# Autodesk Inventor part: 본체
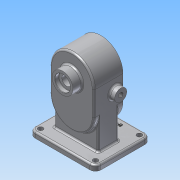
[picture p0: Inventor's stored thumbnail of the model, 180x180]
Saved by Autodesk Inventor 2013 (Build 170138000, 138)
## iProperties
Created: 2020-09
Part Number: 본체
Material: 알루미늄 6061
Document SubType Name: Modeling
Designer: Administrator
Density: 2.71 g/cm^3
Mass: 1445.8 g
Surface Area: 785.637 cm^2
Volume: 533.506 cm^3
Author: Administrator
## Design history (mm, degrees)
sketch "스케치1"
  geometry: L1 (-50, -60)-(50, -60); L2 (50, -60)-(50, 60); L3 (50, 60)-(-50, 60); L4 (-50, 60)-(-50, -60); L5 (-50, -60)-(50, 60); L6 (50, -60)-(-50, 60); 1 further point
  constraints: 12 end point, 2 midpoint, 2 parallel, 1 horizontal, 1 perpendicular
  dimensions: "d0" = 100 distance of L1.start L1.end; "d2" = 120 distance of L1.end L2.end
extrude "돌출1" new body sketch "스케치1" distance "d3" = 10; taper "d4" = 0 deg
sketch "스케치2"
  geometry: L1 (-40, 112)-(-40, 68); L2 (40, 112)-(40, 68); L3 (60, 0)-(-60, 0) reference; A1 r 40 centre (0, 112) between (40, 112) and (-40, 112); A2 r 40 centre (0, 68) between (-40, 68) and (40, 68); 2 further points
  constraints: 4 end point, 4 point on circle, 4 tangent, 2 centre point, 2 vertical alignment, 1 equal radius, 1 midpoint
  dimensions: "d5" = 80 diameter of A1; "d7" = 44 distance of A2.centre A1.centre; "d8" = 112 distance from line of L3 A1.centre
extrude "돌출2" join sketch "스케치2" distance "d9" = 20; taper "d11" = 0 deg; dims "d10" = 33, "d12" = 0
sketch "스케치3"
  geometry: C1 r 19 at (112, 0); A1 r 40 centre (112, 0) between (112, -40) and (112, 40) reference; 1 further point
  constraints: 1 centre point, 1 coincident
  dimensions: "d13" = 38 diameter of C1
extrude "돌출3" join sketch "스케치3" distance "d15" = 17; taper "d16" = 0 deg
sketch "스케치4"
  geometry: L1 (-112, -24)-(-68, -24); L2 (-112, 24)-(-68, 24); A1 r 40 centre (-112, 0) between (-112, 40) and (-112, -40) reference; A2 r 40 centre (-68, 0) between (-68, -40) and (-68, 40) reference; A3 r 24 centre (-112, 0) between (-112, -24) and (-112, 24); A4 r 24 centre (-68, 0) between (-68, -24) and (-68, 24); 1 further point
  constraints: 4 end point, 4 point on circle, 4 tangent, 2 centre point, 2 coincident, 1 equal radius
  dimensions: "d17" = 48 diameter of A3
extrude "돌출4" cut sketch "스케치4" distance "d19" = 29; taper "d20" = 0 deg
sketch "스케치5"
  geometry: C1 r 19 at (0, 0) reference; C2 r 14 at (0, 0); 1 further point
  constraints: 1 centre point, 1 coincident
  dimensions: "d21" = 28 diameter of C2
extrude "돌출5" cut sketch "스케치5" distance "d23" = 7.3; taper "d24" = 0 deg
sketch "스케치6"
  geometry: C1 r 12.5 at (-112, 0); A1 r 24 centre (-112, 0) between (-112, 24) and (-112, -24) reference; 1 further point
  constraints: 1 centre point, 1 coincident
  dimensions: "d25" = 25 diameter of C1
extrude "돌출6" cut sketch "스케치6" distance "d27" = 15; taper "d28" = 0 deg
sketch "스케치7"
  geometry: C1 r 14 at (0, 0) reference; C2 r 8.5 at (0, 0); 1 further point
  constraints: 1 centre point, 1 coincident
  dimensions: "d29" = 17 diameter of C2
extrude "돌출7" cut sketch "스케치7" stored distance "d31" = 15; taper "d32" = 0 deg
sketch "스케치8"
  geometry: C1 r 12.5 at (-68, 0); A1 r 24 centre (-68, 0) between (-68, -24) and (-68, 24) reference; 1 further point
  constraints: 1 centre point, 1 coincident
  dimensions: "d33" = 25 diameter of C1
extrude "돌출8" cut sketch "스케치8" distance "d35" = 15; taper "d36" = 0 deg
sketch "스케치9"
  geometry: L1 (-25, -40)-(12, -40); L2 (12, -40)-(12, 40); L3 (12, 40)-(-25, 40); L4 (-25, 40)-(-25, -40); L5 (-50, 60)-(-50, -60) reference; 2 further points
  constraints: 8 end point, 2 parallel, 1 horizontal, 1 horizontal alignment, 1 midpoint, 1 perpendicular
  dimensions: "d37" = 25 distance between parallel lines of L4 L5; "d38" = 37 distance of L2.end L3.end; "d39" = 80 distance of L1.end L2.end
extrude "돌출9" join sketch "스케치9" stored distance "d40" = 15; taper "d41" = 0 deg
fillet "모깎기1" dims "d42" = 3
fillet "모깎기2" dims "d43" = 10
fillet "모깎기3" dims "d44" = 3
fillet "모깎기4" dims "d45" = 3
fillet "모깎기5" dims "d46" = 3
fillet "모깎기6" dims "d47" = 3
fillet "모깎기7" dims "d48" = 3
chamfer "모따기1" distance "d49" = 0.7; stored, may be unused: second distance "d50" = 2, angle "d51" = 30 deg
chamfer "모따기2" distance "d52" = 1; stored, may be unused: second distance "d53" = 2, angle "d54" = 45 deg
chamfer "모따기3" distance "d55" = 1; stored, may be unused: second distance "d56" = 2, angle "d57" = 45 deg
sketch "스케치10"
  geometry: L1 (-50, 44)-(0, 44) reference; L2 (-60, -68)-(20, -68) reference; L3 (0, 44)-(0, 0) reference; C1 r 11 at (-14, 22); 2 further points
  constraints: 1 centre point, 1 midpoint
  dimensions: "d58" = 22 diameter of C1; "d92" = 22 distance from line of L1 C1.centre; "d93" = 14 distance from line of L3 C1.centre
extrude "돌출10" join sketch "스케치10" distance "d60" = 10; taper "d61" = 0 deg
sketch "스케치11"
  geometry: C1 r 11 at (0, 0) reference; 1 further point
hole "구멍1" sketch "스케치11" at (0, 0) diameter "d62" = 8.376; stored, may be unused: countersink angle "d66" = 90 deg, drill point angle "d68" = 0 deg; dims "d63" = 100, "d64" = 4, "d65" = 2, "d67" = 8
fillet "모깎기8" dims "d69" = 3
sketch "스케치12"
  geometry: A1 r 40 centre (-112, 0) between (-112, 40) and (-112, -40) reference; A2 r 40 centre (-68, 0) between (-68, -40) and (-68, 40) reference; A3 r 31 centre (-112, 0) between (-143, 0) and (-112, 31); A4 r 31 centre (-68, 0) between (-37, 0) and (-68, -31); 3 further points
  constraints: 6 point on circle, 2 centre point, 2 coincident
  dimensions: "d70" = 62 diameter of A3; "d72" = 62 diameter of A4
hole "구멍2" sketch "스케치12" at (-143, 0), (-37, 0), (-68, -31), (-68, 31), (-112, 31), (-112, -31) diameter "d73" = 4.134; stored, may be unused: countersink angle "d77" = 90 deg, drill point angle "d79" = 118 deg; dims "d74" = 10, "d75" = 4, "d76" = 2, "d78" = 12
fillet "모깎기9" dims "d80" = 3
sketch "스케치13"
  geometry: A1 r 10 centre (-40, -50) between (-50, -50) and (-40, -60) reference; A2 r 10 centre (-40, 50) between (-40, 60) and (-50, 50) reference; A3 r 10 centre (40, -50) between (40, -60) and (50, -50) reference; A4 r 10 centre (40, 50) between (50, 50) and (40, 60) reference; 1 further point
hole "구멍3" sketch "스케치13" at (-40, -50), (-40, 50), (40, 50), (40, -50) diameter "d81" = 9; stored, may be unused: countersink angle "d85" = 90 deg, drill point angle "d87" = 118 deg; dims "d82" = 10, "d83" = 4, "d84" = 2, "d86" = 12
sketch "스케치14"
  geometry: L1 (50, -50)-(50, 50) reference; L2 (-40, -60)-(40, -60) reference; 2 further points
  constraints: 1 other
  dimensions: "d88" = 12 distance from line of L1 point (38, 0); "d89" = 60 distance from line of L2 point (38, 0)
feature "엠보싱1" sketch "스케치14" dims "d0" = 100, "d2" = 120, "d90" = 0.5, "d91" = 0
fillet "모깎기10" dims "d94" = 0.5
node "솔리드1"
mirror "대칭1"
